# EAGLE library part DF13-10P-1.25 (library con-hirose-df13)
DF13-10P 1.25mm Pitch Miniature Crimping Connector.
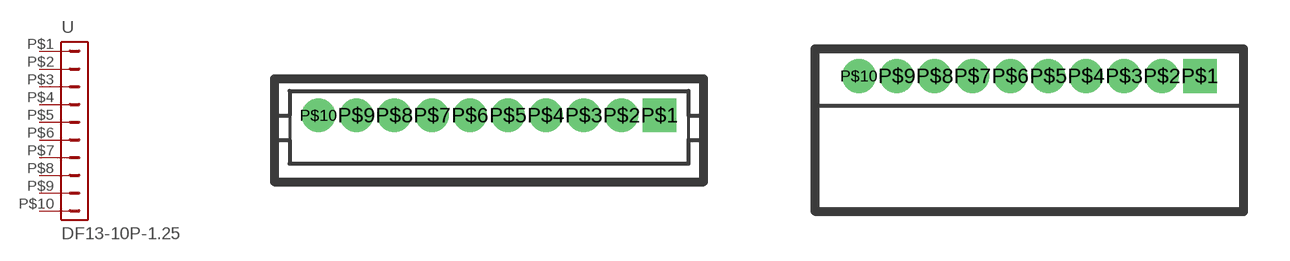
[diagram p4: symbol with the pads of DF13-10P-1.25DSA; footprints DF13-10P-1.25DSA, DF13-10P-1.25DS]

Designator prefix -

## DF13-10P-1.25DSA  [DF13-10P-1.25DSA]
P$1  1  pas
P$2  2  pas
P$3  3  pas
P$4  4  pas
P$5  5  pas
P$6  6  pas
P$7  7  pas
P$8  8  pas
P$9  9  pas
P$10  10  pas

## DF13-10P-1.25DS  [DF13-10P-1.25DS]
Pads as for DF13-10P-1.25DSA

## DF13-10P-1.25V  [DF13C-10P-1.25V]
Pads as for DF13-10P-1.25DSA

## DF13-10P-1.25H  [DF13A-10P-1.25H]
Pads as for DF13-10P-1.25DSA

## Footprint DF13-10P-1.25DSA (pad centres in mm)
Single Row Straight Pin Header (Through hole)
drill 0.6 pad 1.016 square: P$1 5.625,0
drill 0.6 pad 1.016 round: P$2 4.375,0; P$3 3.125,0; P$4 1.875,0; P$5 0.625,0; P$6 -0.625,0; P$7 -1.875,0; P$8 -3.125,0; P$9 -4.375,0; P$10 -5.625,0

## Footprint DF13-10P-1.25DS (pad centres in mm)
Single Row Right Angle Pin Header (Through hole)
drill 0.6 pad 1.016 square: P$1 5.625,0
drill 0.6 pad 1.016 round: P$2 4.375,0; P$3 3.125,0; P$4 1.875,0; P$5 0.625,0; P$6 -0.625,0; P$7 -1.875,0; P$8 -3.125,0; P$9 -4.375,0; P$10 -5.625,0

## Footprint DF13C-10P-1.25V (pad centres in mm)
Single Row Straight Pin Header (SMT)
smd 1.6 x 2.2: M$0 8.075,-1.8; M$1 -8.075,-1.8
smd 0.7 x 1.8: P$1 -5.625,0.9; P$2 -4.375,0.9; P$3 -3.125,0.9; P$4 -1.875,0.9; P$5 -0.625,0.9; P$6 0.625,0.9; P$7 1.875,0.9; P$8 3.125,0.9; P$9 4.375,0.9; P$10 5.625,0.9

## Footprint DF13A-10P-1.25H (pad centres in mm)
Single Row Straight Pin Header (SMT)
smd 1.6 x 2.2: M$0 -7.975,2.4; M$1 7.975,2.4
smd 0.7 x 1.8: P$1 -5.625,-0.9; P$2 -4.375,-0.9; P$3 -3.125,-0.9; P$4 -1.875,-0.9; P$5 -0.625,-0.9; P$6 0.625,-0.9; P$7 1.875,-0.9; P$8 3.125,-0.9; P$9 4.375,-0.9; P$10 5.625,-0.9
